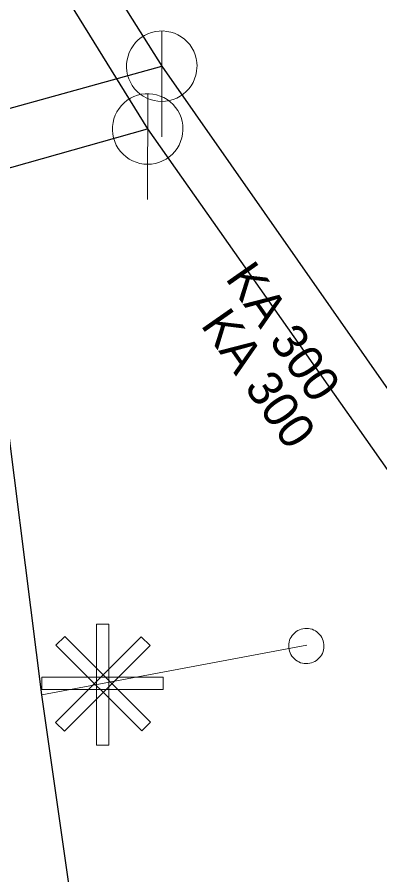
# Model space of a CAD drawing. Extents: x -809028 to -807737, y -990545 to -989489.
# Drawn here: x -808603 to -808592.72, y -989740.24 to -989715.91 of the extents above; entities that cross this region are included whole.
import ezdxf

# ---------------------------------------------------------------- set-up
doc = ezdxf.new("R2010")
doc.units = 0
doc.header["$LTSCALE"] = 0.32
for name, color, linetype, lineweight in [('1', 7, 'Continuous', 13), ('12', 7, 'Continuous', 13), ('13', 7, 'Continuous', 13), ('14', 7, 'Continuous', 25), ('17', 7, 'Continuous', 25), ('22', 7, 'Continuous', 13), ('23', 7, 'Continuous', 13)]:
    doc.layers.add(name, color=color, linetype=linetype, lineweight=lineweight)

msp = doc.modelspace()

# ---------------------------------------------------------------- linework, layer by layer
at = {"layer": '12'}
for points in [[(-808600.744, -989733.125), (-808600.394, -989733.125), (-808600.394, -989736.56), (-808600.744, -989736.56)], [(-808599.478, -989733.489), (-808599.23, -989733.737), (-808601.659, -989736.166), (-808601.906, -989735.918)], [(-808601.897, -989733.728), (-808601.65, -989733.48), (-808599.221, -989735.909), (-808599.468, -989736.157)], [(-808598.86, -989734.634), (-808598.86, -989734.984), (-808602.295, -989734.984), (-808602.295, -989734.634)]]:
    msp.add_lwpolyline(points, close=True, dxfattribs=at)
at = {"layer": '13'}
msp.add_line((-808602.293, -989735.129), (-808594.783, -989733.721), dxfattribs=at)
at = {"layer": '14'}
for p, q in [((-808624.888, -989675.946), (-808598.899, -989717.298)), ((-808618.594, -989687.859), (-808599.298, -989719.079)), ((-808598.899, -989717.298), (-808588.646, -989731.98)), ((-808599.298, -989719.079), (-808589.636, -989732.835))]:
    msp.add_line(p, q, dxfattribs=at)
for points in [[(-808633.069, -989727.257), (-808620.411, -989723.296), (-808619.305, -989722.982), (-808614.478, -989721.613), (-808613.777, -989721.419), (-808598.899, -989717.298)], [(-808632.272, -989728.388), (-808627.164, -989726.947), (-808626.507, -989726.761), (-808619.273, -989724.719), (-808618.7, -989724.557), (-808613.168, -989722.995), (-808612.517, -989722.811), (-808599.298, -989719.079)]]:
    msp.add_lwpolyline(points, dxfattribs=at)
at = {"layer": '17'}
msp.add_lwpolyline([(-808593.698, -989796.145), (-808595.09, -989785.605), (-808602.293, -989735.129), (-808603.549, -989725.298)], dxfattribs=at)
at = {"layer": '22'}
for p, q in [((-808598.899, -989719.298), (-808598.898, -989716.298)), ((-808599.298, -989721.079), (-808599.297, -989718.079))]:
    msp.add_line(p, q, dxfattribs=at)
for points in [[(-808597.899, -989717.298), (-808597.904, -989717.189), (-808597.922, -989717.081), (-808597.952, -989716.975), (-808597.992, -989716.874), (-808598.044, -989716.777), (-808598.106, -989716.687), (-808598.178, -989716.604), (-808598.258, -989716.53), (-808598.346, -989716.464), (-808598.44, -989716.409), (-808598.54, -989716.364), (-808598.645, -989716.331), (-808598.752, -989716.309), (-808598.861, -989716.299), (-808598.971, -989716.301), (-808599.079, -989716.315), (-808599.186, -989716.34), (-808599.289, -989716.377), (-808599.387, -989716.426), (-808599.479, -989716.484), (-808599.565, -989716.553), (-808599.642, -989716.63), (-808599.711, -989716.716), (-808599.77, -989716.808), (-808599.818, -989716.906), (-808599.855, -989717.009), (-808599.881, -989717.116), (-808599.895, -989717.224), (-808599.898, -989717.334), (-808599.888, -989717.443), (-808599.867, -989717.55), (-808599.833, -989717.654), (-808599.789, -989717.754), (-808599.734, -989717.849), (-808599.668, -989717.937), (-808599.594, -989718.017), (-808599.511, -989718.089), (-808599.421, -989718.151), (-808599.325, -989718.203), (-808599.223, -989718.244), (-808599.118, -989718.274), (-808599.01, -989718.292), (-808598.9, -989718.298), (-808598.791, -989718.292), (-808598.683, -989718.274), (-808598.578, -989718.245), (-808598.476, -989718.204), (-808598.379, -989718.152), (-808598.289, -989718.09), (-808598.206, -989718.019), (-808598.131, -989717.939), (-808598.066, -989717.851), (-808598.01, -989717.757), (-808597.966, -989717.657), (-808597.932, -989717.553), (-808597.91, -989717.445), (-808597.9, -989717.336)], [(-808598.298, -989719.079), (-808598.303, -989718.97), (-808598.321, -989718.862), (-808598.351, -989718.756), (-808598.391, -989718.655), (-808598.443, -989718.558), (-808598.505, -989718.468), (-808598.577, -989718.385), (-808598.657, -989718.311), (-808598.745, -989718.245), (-808598.839, -989718.19), (-808598.939, -989718.145), (-808599.044, -989718.112), (-808599.151, -989718.09), (-808599.26, -989718.08), (-808599.37, -989718.082), (-808599.478, -989718.096), (-808599.585, -989718.121), (-808599.688, -989718.158), (-808599.786, -989718.207), (-808599.878, -989718.265), (-808599.964, -989718.334), (-808600.041, -989718.411), (-808600.11, -989718.497), (-808600.169, -989718.589), (-808600.217, -989718.687), (-808600.254, -989718.79), (-808600.28, -989718.897), (-808600.294, -989719.005), (-808600.297, -989719.115), (-808600.287, -989719.224), (-808600.266, -989719.331), (-808600.232, -989719.435), (-808600.188, -989719.535), (-808600.133, -989719.63), (-808600.067, -989719.718), (-808599.993, -989719.798), (-808599.91, -989719.87), (-808599.82, -989719.932), (-808599.724, -989719.984), (-808599.622, -989720.025), (-808599.517, -989720.055), (-808599.409, -989720.073), (-808599.299, -989720.079), (-808599.19, -989720.073), (-808599.082, -989720.055), (-808598.977, -989720.026), (-808598.875, -989719.985), (-808598.778, -989719.933), (-808598.688, -989719.871), (-808598.605, -989719.8), (-808598.53, -989719.72), (-808598.465, -989719.632), (-808598.409, -989719.538), (-808598.365, -989719.438), (-808598.331, -989719.334), (-808598.309, -989719.226), (-808598.299, -989719.117)]]:
    msp.add_lwpolyline(points, close=True, dxfattribs=at)
at = {"layer": '23'}
for points in [[(-808594.31, -989733.65), (-808594.323, -989733.598), (-808594.342, -989733.549), (-808594.365, -989733.503), (-808594.393, -989733.459), (-808594.425, -989733.418), (-808594.463, -989733.38), (-808594.503, -989733.347), (-808594.546, -989733.318), (-808594.592, -989733.294), (-808594.64, -989733.274), (-808594.691, -989733.259), (-808594.743, -989733.251), (-808594.795, -989733.247), (-808594.846, -989733.25), (-808594.898, -989733.256), (-808594.95, -989733.27), (-808594.998, -989733.287), (-808595.046, -989733.312), (-808595.089, -989733.338), (-808595.131, -989733.37), (-808595.169, -989733.409), (-808595.202, -989733.449), (-808595.231, -989733.493), (-808595.256, -989733.538), (-808595.275, -989733.586), (-808595.288, -989733.638), (-808595.297, -989733.688), (-808595.301, -989733.741), (-808595.298, -989733.793), (-808595.291, -989733.845), (-808595.279, -989733.895), (-808595.26, -989733.945), (-808595.237, -989733.992), (-808595.21, -989734.036), (-808595.177, -989734.076), (-808595.14, -989734.114), (-808595.1, -989734.148), (-808595.056, -989734.177), (-808595.01, -989734.201)], [(-808595.046, -989733.312), (-808595.089, -989733.338), (-808595.131, -989733.37), (-808595.169, -989733.409), (-808595.202, -989733.449), (-808595.231, -989733.493), (-808595.256, -989733.538), (-808595.275, -989733.586), (-808595.288, -989733.638), (-808595.297, -989733.688), (-808595.301, -989733.741), (-808595.298, -989733.793), (-808595.291, -989733.845), (-808595.279, -989733.895), (-808595.26, -989733.945), (-808595.237, -989733.992), (-808595.21, -989734.036), (-808595.177, -989734.076), (-808595.14, -989734.114), (-808595.1, -989734.148), (-808595.056, -989734.177), (-808595.01, -989734.201), (-808594.962, -989734.221), (-808594.911, -989734.234), (-808594.86, -989734.244), (-808594.807, -989734.247), (-808594.756, -989734.244), (-808594.704, -989734.237), (-808594.654, -989734.224), (-808594.604, -989734.206), (-808594.556, -989734.183), (-808594.513, -989734.155), (-808594.471, -989734.122), (-808594.434, -989734.087), (-808594.401, -989734.045), (-808594.371, -989734.003), (-808594.347, -989733.957), (-808594.327, -989733.907), (-808594.313, -989733.857), (-808594.305, -989733.805)], [(-808595.01, -989734.201), (-808594.962, -989734.221), (-808594.911, -989734.234), (-808594.86, -989734.244), (-808594.807, -989734.247), (-808594.756, -989734.244), (-808594.704, -989734.237), (-808594.654, -989734.224), (-808594.604, -989734.206), (-808594.556, -989734.183), (-808594.513, -989734.155), (-808594.471, -989734.122), (-808594.434, -989734.087), (-808594.401, -989734.045), (-808594.371, -989734.003), (-808594.347, -989733.957), (-808594.327, -989733.907), (-808594.313, -989733.857), (-808594.305, -989733.805), (-808594.302, -989733.753), (-808594.304, -989733.701), (-808594.31, -989733.65), (-808594.323, -989733.598), (-808594.342, -989733.549), (-808594.365, -989733.503), (-808594.393, -989733.459), (-808594.425, -989733.418), (-808594.463, -989733.38), (-808594.503, -989733.347), (-808594.546, -989733.318), (-808594.592, -989733.294), (-808594.64, -989733.274), (-808594.691, -989733.259), (-808594.743, -989733.251), (-808594.795, -989733.247), (-808594.846, -989733.25), (-808594.898, -989733.256), (-808594.95, -989733.27), (-808594.998, -989733.287), (-808595.046, -989733.312)], [(-808594.305, -989733.805), (-808594.302, -989733.753), (-808594.304, -989733.701), (-808594.31, -989733.65)]]:
    msp.add_lwpolyline(points, dxfattribs=at)

# ---------------------------------------------------------------- texts
at = {"layer": '1'}
for p in [(-808597.117, -989723.316), (-808597.815, -989724.643)]:
    msp.add_text('KA 300', height=1, rotation=305, dxfattribs=at).set_placement(p)

doc.saveas('drawing.dxf')
